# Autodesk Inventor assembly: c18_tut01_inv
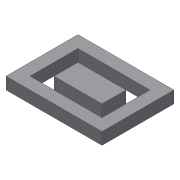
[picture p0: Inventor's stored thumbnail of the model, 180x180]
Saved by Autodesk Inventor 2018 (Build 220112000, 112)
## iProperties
Created: 2017-06
Part Number: c18_tut01_inv
Document SubType Name: Assembly
Designer: CADCIM 00
Author: CADCIM 00
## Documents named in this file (3)
- E:\_Deepak\Inventor\Autodesk Inventor_2017_Project\Resources\Inventor_2018_tut\c18_Inv_tut_2018\c15_tut01_inv\c18_tut01_inv\c18_tut01_inv.iam
- E:\_Deepak\Inventor\Autodesk Inventor_2017_Project\Resources\Inventor_2018_Part\c14_Inv_2018\c14_inv_2018_prt\Outer Plate.ipt
- E:\_Deepak\Inventor\Autodesk Inventor_2017_Project\Resources\Inventor_2018_Part\c14_Inv_2018\c14_inv_2018_prt\Inner Plate.ipt
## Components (2 placed, 2 different names)
1. Outer Plate:1 — Flush:1, Flush:2, Mate:1, Mate:2, Mate:3, Mate:4
2. Inner Plate:1 — Flush:1, Flush:2, Mate:1, Mate:2, Mate:3, Mate:4
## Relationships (6: Mate 4, Flush 2)
- Flush:1: Outer Plate:1 ↔ Inner Plate:1
- Flush:2: Outer Plate:1 ↔ Inner Plate:1
- Mate:1: Outer Plate:1 ↔ Inner Plate:1
- Mate:2: Outer Plate:1 ↔ Inner Plate:1
- Mate:3: Outer Plate:1 ↔ Inner Plate:1
- Mate:4: Outer Plate:1 ↔ Inner Plate:1
